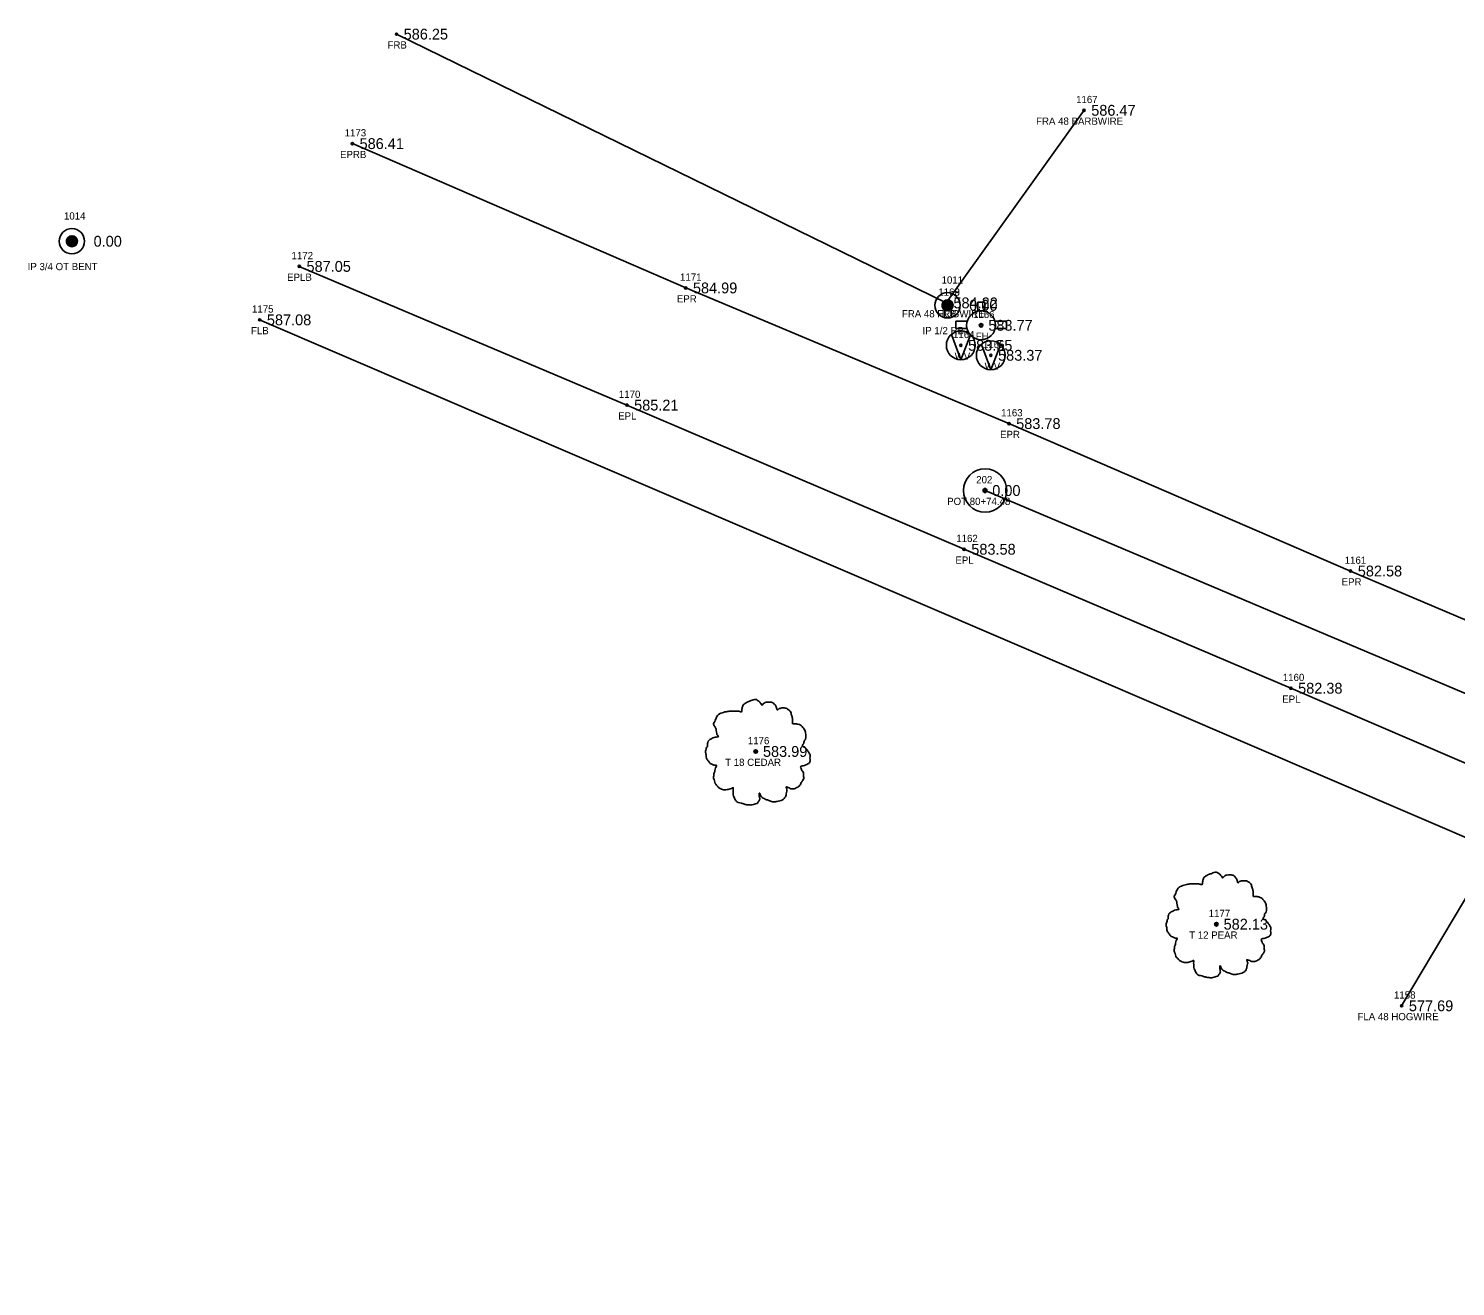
# Model space of a CAD drawing. Extents: x 1664393 to 1667175, y 987029 to 988607.
# Drawn here: x 1664830.8 to 1665028.1, y 987885.7 to 988059.7 of the extents above; entities that cross this region are included whole.
import ezdxf

# ---------------------------------------------------------------- set-up
doc = ezdxf.new("R2010")
doc.units = 0
for name, color, linetype in [('RD_EX_DV_Prop_txCode', 7, 'Continuous'), ('RD_EX_DV_PropPin', 7, 'Continuous'), ('RD_EX_Fence_Other', 7, 'Continuous'), ('RD_EX_Fence_Other_txCode', 7, 'Continuous'), ('RD_EX_Road', 7, 'Continuous'), ('RD_EX_Road_txCode', 7, 'Continuous'), ('RD_EX_TX_DV_Prop_ELEV', 7, 'Continuous'), ('RD_EX_TX_Fence_Other_ELEV', 7, 'Continuous'), ('RD_EX_TX_Road_ELEV', 7, 'Continuous'), ('RD_EX_TX_UT_ELEV', 7, 'Continuous'), ('RD_EX_TX_VEG_ELEV', 7, 'Continuous'), ('RD_EX_UT', 7, 'Continuous'), ('RD_EX_UT_txCode', 7, 'Continuous'), ('RD_EX_VEG', 7, 'Continuous'), ('RD_EX_VEG_txCode', 7, 'Continuous'), ('RD_HC_Cl', 7, 'Continuous'), ('RD_HC_Data', 7, 'Continuous'), ('RD_HC_Survey_ELEV', 7, 'Continuous'), ('RD_HC_txCode', 7, 'Continuous'), ('RD_SMD_Locator', 7, 'Continuous')]:
    doc.layers.add(name, color=color, linetype=linetype)

msp = doc.modelspace()

# ---------------------------------------------------------------- linework, layer by layer
at = {"layer": 'RD_EX_DV_PropPin'}
for p, q in [((1664836.03, 988030.1), (1664836.03, 988030.49)), ((1664836.06, 988030), (1664836.06, 988030.59)), ((1664836.1, 988029.92), (1664836.1, 988030.66)), ((1664836.13, 988029.87), (1664836.13, 988030.72)), ((1664836.17, 988029.82), (1664836.17, 988030.77)), ((1664836.2, 988029.78), (1664836.2, 988030.81)), ((1664836.24, 988029.74), (1664836.24, 988030.84)), ((1664836.27, 988029.71), (1664836.27, 988030.88)), ((1664836.31, 988029.68), (1664836.31, 988030.9)), ((1664836.34, 988029.66), (1664836.34, 988030.93)), ((1664836.38, 988029.64), (1664836.38, 988030.95)), ((1664836.41, 988029.62), (1664836.41, 988030.97)), ((1664836.45, 988029.6), (1664836.45, 988030.99)), ((1664836.48, 988029.59), (1664836.48, 988031)), ((1664836.52, 988029.57), (1664836.52, 988031.01)), ((1664836.55, 988029.56), (1664836.55, 988031.03)), ((1664836.59, 988029.55), (1664836.59, 988031.03)), ((1664836.62, 988029.55), (1664836.62, 988031.04)), ((1664836.66, 988029.54), (1664836.66, 988031.05)), ((1664836.69, 988029.54), (1664836.69, 988031.05)), ((1664836.73, 988029.53), (1664836.73, 988031.05)), ((1664836.76, 988029.53), (1664836.76, 988031.05)), ((1664836.8, 988029.53), (1664836.8, 988031.05)), ((1664836.83, 988029.54), (1664836.83, 988031.05)), ((1664836.87, 988029.54), (1664836.87, 988031.05)), ((1664836.9, 988029.55), (1664836.9, 988031.04)), ((1664836.94, 988029.55), (1664836.94, 988031.03)), ((1664836.97, 988029.56), (1664836.97, 988031.03)), ((1664837.01, 988029.57), (1664837.01, 988031.01)), ((1664837.04, 988029.59), (1664837.04, 988031)), ((1664837.08, 988029.6), (1664837.08, 988030.99)), ((1664837.11, 988029.62), (1664837.11, 988030.97)), ((1664837.15, 988029.64), (1664837.15, 988030.95)), ((1664837.18, 988029.66), (1664837.18, 988030.93)), ((1664837.22, 988029.68), (1664837.22, 988030.9)), ((1664837.25, 988029.71), (1664837.25, 988030.88)), ((1664837.29, 988029.74), (1664837.29, 988030.84)), ((1664837.32, 988029.78), (1664837.32, 988030.81)), ((1664837.36, 988029.82), (1664837.36, 988030.77)), ((1664837.39, 988029.87), (1664837.39, 988030.72)), ((1664837.43, 988029.92), (1664837.43, 988030.66)), ((1664837.46, 988030), (1664837.46, 988030.59)), ((1664837.5, 988030.1), (1664837.5, 988030.49)), ((1664957.14, 988021.23), (1664957.14, 988021.62)), ((1664957.17, 988021.13), (1664957.17, 988021.72)), ((1664957.21, 988021.06), (1664957.21, 988021.79)), ((1664957.24, 988021), (1664957.24, 988021.85)), ((1664957.28, 988020.95), (1664957.28, 988021.9)), ((1664957.31, 988020.91), (1664957.31, 988021.94)), ((1664957.35, 988020.87), (1664957.35, 988021.98)), ((1664957.38, 988020.84), (1664957.38, 988022.01)), ((1664957.42, 988020.82), (1664957.42, 988022.04)), ((1664957.46, 988020.79), (1664957.46, 988022.06)), ((1664957.49, 988020.77), (1664957.49, 988022.08)), ((1664957.53, 988020.75), (1664957.53, 988022.1)), ((1664957.56, 988020.73), (1664957.56, 988022.12)), ((1664957.6, 988020.72), (1664957.6, 988022.13)), ((1664957.63, 988020.7), (1664957.63, 988022.15)), ((1664957.67, 988020.69), (1664957.67, 988022.16)), ((1664957.7, 988020.68), (1664957.7, 988022.17)), ((1664957.74, 988020.68), (1664957.74, 988022.17)), ((1664957.77, 988020.67), (1664957.77, 988022.18)), ((1664957.81, 988020.67), (1664957.81, 988022.18)), ((1664957.84, 988020.66), (1664957.84, 988022.19)), ((1664957.88, 988020.66), (1664957.88, 988022.19)), ((1664957.91, 988020.66), (1664957.91, 988022.19)), ((1664957.95, 988020.67), (1664957.95, 988022.18)), ((1664957.98, 988020.67), (1664957.98, 988022.18)), ((1664958.02, 988020.68), (1664958.02, 988022.17)), ((1664958.05, 988020.68), (1664958.05, 988022.17)), ((1664958.09, 988020.69), (1664958.09, 988022.16)), ((1664958.12, 988020.7), (1664958.12, 988022.15)), ((1664958.16, 988020.72), (1664958.16, 988022.13)), ((1664958.19, 988020.73), (1664958.19, 988022.12)), ((1664958.23, 988020.75), (1664958.23, 988022.1)), ((1664958.26, 988020.77), (1664958.26, 988022.08)), ((1664958.3, 988020.79), (1664958.3, 988022.06)), ((1664958.33, 988020.82), (1664958.33, 988022.04)), ((1664958.37, 988020.84), (1664958.37, 988022.01)), ((1664958.4, 988020.87), (1664958.4, 988021.98)), ((1664958.44, 988020.91), (1664958.44, 988021.94)), ((1664958.47, 988020.95), (1664958.47, 988021.9)), ((1664958.51, 988021), (1664958.51, 988021.85)), ((1664958.54, 988021.06), (1664958.54, 988021.79)), ((1664958.58, 988021.13), (1664958.58, 988021.72)), ((1664958.61, 988021.23), (1664958.61, 988021.62))]:
    msp.add_line(p, q, dxfattribs=at)
for centre, radius in [((1664836.76, 988030.29), 1.75), ((1664836.76, 988030.29), 0.761), ((1664957.88, 988021.43), 1.75), ((1664957.88, 988021.43), 0.761)]:
    msp.add_circle(centre, radius, dxfattribs=at)
at = {"layer": 'RD_EX_Fence_Other'}
for points in [[(1664976.76, 988048.41), (1664957.7, 988021.76), (1664957.7, 988021.76), (1664881.65, 988058.95)], [(1665020.7, 987924.5), (1665033.54, 987946.09), (1664862.73, 988019.42)]]:
    msp.add_lwpolyline(points, dxfattribs=at)
at = {"layer": 'RD_EX_Road'}
for points in [[(1665506.06, 987776.52), (1665471.95, 987789.57), (1665426.52, 987809.19), (1665380.33, 987828.78), (1665335.61, 987847.53), (1665288.25, 987866.82), (1665242.34, 987886.56), (1665197.07, 987906.16), (1665152.2, 987925.43), (1665127.55, 987936.7), (1665104.5, 987945.2), (1665059.19, 987965.3), (1665013.63, 987984.66), (1664966.38, 988005.06), (1664921.66, 988023.83), (1664875.55, 988043.8)], [(1665498.75, 987759.37), (1665465.87, 987774.2), (1665419.78, 987793.88), (1665373.62, 987813.14), (1665327.95, 987832.31), (1665281.42, 987852.3), (1665236.13, 987871.34), (1665189.6, 987890.71), (1665143.92, 987909.97), (1665117.43, 987920.99), (1665086.22, 987934.27), (1665051.62, 987948.55), (1665005.38, 987968.44), (1664960.17, 987987.67), (1664913.53, 988007.62), (1664868.21, 988026.81)]]:
    msp.add_lwpolyline(points, dxfattribs=at)
at = {"layer": 'RD_EX_UT'}
for p, q in [((1664962.06, 988021.88), (1664962.06, 988020.61)), ((1664963.06, 988021.88), (1664962.06, 988021.88)), ((1664963.06, 988020.58), (1664963.06, 988021.88)), ((1664960.6, 988019.23), (1664959.04, 988019.23)), ((1664959.04, 988019.23), (1664959.04, 988018.23)), ((1664959.04, 988018.23), (1664960.56, 988018.23)), ((1664966.04, 988019.23), (1664964.43, 988019.23)), ((1664964.47, 988018.23), (1664966.04, 988018.23)), ((1664966.04, 988018.23), (1664966.04, 988019.23)), ((1664959.72, 988013.9), (1664958.42, 988017.38)), ((1664959.72, 988013.9), (1664961.05, 988017.35)), ((1664963.87, 988012.51), (1664962.57, 988016)), ((1664963.87, 988012.51), (1664965.19, 988015.96))]:
    msp.add_line(p, q, dxfattribs=at)
for centre, radius in [((1664962.52, 988018.66), 2), ((1664959.72, 988015.89), 2), ((1664962.52, 988018.66), 0.25), ((1664963.87, 988014.51), 2)]:
    msp.add_circle(centre, radius, dxfattribs=at)
for start, end in [(74.2455, 103.2128), (163.3387, 192.315), (347.685, 16.6613)]:
    msp.add_arc((1664962.52, 988018.66), 2, start, end, dxfattribs=at)
at = {"layer": 'RD_EX_VEG'}
for centre, radius in [((1664931.35, 987959.69), 0.25), ((1664931.34, 987959.67), 0.0001), ((1664995.07, 987935.79), 0.25), ((1664995.06, 987935.77), 0.0001)]:
    msp.add_circle(centre, radius, dxfattribs=at)
for points in [[(1664931.48, 987966.86), (1664931.18, 987966.88), (1664930.86, 987966.78), (1664930.61, 987966.68), (1664930.38, 987966.61), (1664930.16, 987966.51), (1664929.86, 987966.33), (1664929.63, 987966.13), (1664929.51, 987965.88), (1664929.46, 987965.66), (1664929.41, 987965.38), (1664929.41, 987965.21), (1664929.28, 987965.18), (1664929.13, 987965.21), (1664928.88, 987965.28), (1664928.63, 987965.28), (1664928.38, 987965.28), (1664928.03, 987965.26), (1664927.68, 987965.26), (1664927.41, 987965.21), (1664927.08, 987965.16), (1664926.71, 987965.03), (1664926.36, 987964.91), (1664926.06, 987964.66), (1664925.81, 987964.18), (1664925.68, 987963.83), (1664925.53, 987963.58), (1664925.68, 987963.13), (1664925.86, 987962.78), (1664925.88, 987962.58), (1664925.96, 987962.16), (1664926.06, 987961.93), (1664926.18, 987961.73), (1664926.11, 987961.71), (1664925.73, 987961.66), (1664925.43, 987961.56), (1664925.01, 987961.33), (1664924.78, 987961.11), (1664924.68, 987960.78), (1664924.66, 987960.43), (1664924.56, 987960.23), (1664924.48, 987959.96), (1664924.46, 987959.88), (1664924.41, 987959.56), (1664924.51, 987959.11), (1664924.53, 987958.76), (1664924.66, 987958.53), (1664924.81, 987958.36), (1664924.98, 987958.11), (1664925.38, 987957.88), (1664925.71, 987957.78), (1664925.91, 987957.76), (1664925.73, 987957.26), (1664925.68, 987956.91), (1664925.56, 987956.51), (1664925.56, 987956.44), (1664925.51, 987955.96), (1664925.66, 987955.64), (1664925.73, 987955.26), (1664925.91, 987955.04), (1664926.18, 987954.74), (1664926.51, 987954.51), (1664927.01, 987954.39), (1664927.41, 987954.41), (1664927.98, 987954.59), (1664928.23, 987954.66), (1664928.21, 987954.49), (1664928.23, 987954.11), (1664928.23, 987953.69), (1664928.38, 987953.36), (1664928.48, 987953.09), (1664928.63, 987952.84), (1664928.96, 987952.61), (1664929.36, 987952.54), (1664929.78, 987952.39), (1664930.23, 987952.31), (1664930.73, 987952.29), (1664931.33, 987952.44), (1664931.61, 987952.56), (1664931.71, 987952.74), (1664931.91, 987953.11), (1664931.86, 987953.34), (1664931.88, 987953.94), (1664931.98, 987953.76), (1664932.16, 987953.41), (1664932.66, 987953.11), (1664933.06, 987952.94), (1664933.53, 987952.79), (1664933.83, 987952.71), (1664934.31, 987952.79), (1664934.68, 987952.86), (1664935.05, 987952.99), (1664935.35, 987953.26), (1664935.53, 987953.54), (1664935.58, 987953.81), (1664935.65, 987954.19), (1664935.7, 987954.36)], [(1664935.7, 987954.36), (1664935.63, 987954.54), (1664935.58, 987954.79), (1664935.65, 987954.76), (1664935.83, 987954.71), (1664936.1, 987954.59), (1664936.33, 987954.51), (1664936.65, 987954.54), (1664936.93, 987954.64), (1664937.38, 987954.91), (1664937.65, 987955.39), (1664937.93, 987955.79), (1664938, 987956.11), (1664937.95, 987956.34), (1664937.93, 987956.83), (1664937.73, 987957.08), (1664937.68, 987957.21), (1664937.58, 987957.61), (1664937.65, 987957.66), (1664937.93, 987957.71), (1664938.3, 987957.83), (1664938.58, 987957.96), (1664938.8, 987958.13), (1664938.88, 987958.36), (1664938.85, 987958.76), (1664938.9, 987959.16), (1664938.83, 987959.31), (1664938.73, 987959.46), (1664938.65, 987959.66), (1664938.5, 987959.81), (1664938.4, 987959.96), (1664938.3, 987960.06), (1664938.18, 987960.21), (1664938, 987960.33), (1664937.85, 987960.38), (1664937.8, 987960.53), (1664937.95, 987960.73), (1664938, 987960.83), (1664938.03, 987961.06), (1664938.25, 987961.41), (1664938.3, 987961.81), (1664938.25, 987962.23), (1664938.2, 987962.51), (1664938.05, 987962.78), (1664937.85, 987963.03), (1664937.73, 987963.21), (1664937.55, 987963.33), (1664937.23, 987963.46), (1664936.98, 987963.51), (1664936.63, 987963.51), (1664936.43, 987963.56), (1664936.45, 987963.61), (1664936.45, 987963.76), (1664936.45, 987964.03), (1664936.38, 987964.48), (1664936.23, 987964.98), (1664936.23, 987965.01), (1664936.13, 987965.26), (1664935.9, 987965.46), (1664935.73, 987965.56), (1664935.53, 987965.68), (1664935.28, 987965.71), (1664934.98, 987965.71), (1664934.71, 987965.66), (1664934.51, 987965.56), (1664934.33, 987965.43), (1664934.26, 987965.58), (1664934.16, 987965.88), (1664934.11, 987966.03), (1664933.96, 987966.21), (1664933.73, 987966.41), (1664933.28, 987966.53), (1664932.66, 987966.46), (1664932.36, 987966.26), (1664932.21, 987966.08), (1664932.16, 987966.21), (1664931.96, 987966.41), (1664931.86, 987966.58), (1664931.68, 987966.71), (1664931.53, 987966.81), (1664931.43, 987966.86)], [(1664995.2, 987942.96), (1664994.9, 987942.98), (1664994.58, 987942.88), (1664994.33, 987942.78), (1664994.1, 987942.71), (1664993.88, 987942.61), (1664993.58, 987942.43), (1664993.35, 987942.23), (1664993.23, 987941.98), (1664993.18, 987941.76), (1664993.13, 987941.48), (1664993.13, 987941.31), (1664993, 987941.28), (1664992.85, 987941.31), (1664992.6, 987941.38), (1664992.35, 987941.38), (1664992.1, 987941.38), (1664991.75, 987941.36), (1664991.4, 987941.36), (1664991.13, 987941.31), (1664990.8, 987941.26), (1664990.43, 987941.13), (1664990.08, 987941.01), (1664989.78, 987940.76), (1664989.53, 987940.28), (1664989.4, 987939.93), (1664989.25, 987939.68), (1664989.4, 987939.23), (1664989.58, 987938.88), (1664989.6, 987938.68), (1664989.68, 987938.26), (1664989.78, 987938.03), (1664989.9, 987937.83), (1664989.83, 987937.81), (1664989.45, 987937.76), (1664989.15, 987937.66), (1664988.73, 987937.43), (1664988.5, 987937.21), (1664988.4, 987936.88), (1664988.38, 987936.53), (1664988.28, 987936.33), (1664988.21, 987936.06), (1664988.18, 987935.98), (1664988.13, 987935.66), (1664988.23, 987935.21), (1664988.26, 987934.86), (1664988.38, 987934.63), (1664988.53, 987934.46), (1664988.7, 987934.21), (1664989.1, 987933.98), (1664989.43, 987933.88), (1664989.63, 987933.86), (1664989.45, 987933.36), (1664989.4, 987933.01), (1664989.28, 987932.61), (1664989.28, 987932.53), (1664989.23, 987932.06), (1664989.38, 987931.74), (1664989.45, 987931.36), (1664989.63, 987931.14), (1664989.9, 987930.84), (1664990.23, 987930.61), (1664990.73, 987930.49), (1664991.13, 987930.51), (1664991.7, 987930.69), (1664991.95, 987930.76), (1664991.93, 987930.59), (1664991.95, 987930.21), (1664991.95, 987929.79), (1664992.1, 987929.46), (1664992.2, 987929.19), (1664992.35, 987928.94), (1664992.68, 987928.71), (1664993.08, 987928.64), (1664993.5, 987928.49), (1664993.95, 987928.41), (1664994.45, 987928.39), (1664995.05, 987928.54), (1664995.33, 987928.66), (1664995.43, 987928.84), (1664995.63, 987929.21), (1664995.58, 987929.44), (1664995.6, 987930.04), (1664995.7, 987929.86), (1664995.88, 987929.51), (1664996.38, 987929.21), (1664996.78, 987929.04), (1664997.25, 987928.89), (1664997.55, 987928.81), (1664998.03, 987928.89), (1664998.4, 987928.96), (1664998.78, 987929.09), (1664999.08, 987929.36), (1664999.25, 987929.64), (1664999.3, 987929.91), (1664999.38, 987930.29), (1664999.43, 987930.46)], [(1664999.43, 987930.46), (1664999.35, 987930.64), (1664999.3, 987930.89), (1664999.38, 987930.86), (1664999.55, 987930.81), (1664999.83, 987930.69), (1665000.05, 987930.61), (1665000.37, 987930.64), (1665000.65, 987930.74), (1665001.1, 987931.01), (1665001.37, 987931.49), (1665001.65, 987931.89), (1665001.72, 987932.21), (1665001.67, 987932.43), (1665001.65, 987932.93), (1665001.45, 987933.18), (1665001.4, 987933.31), (1665001.3, 987933.71), (1665001.37, 987933.76), (1665001.65, 987933.81), (1665002.02, 987933.93), (1665002.3, 987934.06), (1665002.52, 987934.23), (1665002.6, 987934.46), (1665002.57, 987934.86), (1665002.62, 987935.26), (1665002.55, 987935.41), (1665002.45, 987935.56), (1665002.37, 987935.76), (1665002.22, 987935.91), (1665002.12, 987936.06), (1665002.02, 987936.16), (1665001.9, 987936.31), (1665001.72, 987936.43), (1665001.57, 987936.48), (1665001.52, 987936.63), (1665001.67, 987936.83), (1665001.72, 987936.93), (1665001.75, 987937.16), (1665001.97, 987937.51), (1665002.02, 987937.91), (1665001.97, 987938.33), (1665001.92, 987938.61), (1665001.77, 987938.88), (1665001.57, 987939.13), (1665001.45, 987939.31), (1665001.27, 987939.43), (1665000.95, 987939.56), (1665000.7, 987939.61), (1665000.35, 987939.61), (1665000.15, 987939.66), (1665000.17, 987939.71), (1665000.17, 987939.86), (1665000.17, 987940.13), (1665000.1, 987940.58), (1664999.95, 987941.08), (1664999.95, 987941.11), (1664999.85, 987941.36), (1664999.63, 987941.56), (1664999.45, 987941.66), (1664999.25, 987941.78), (1664999, 987941.81), (1664998.7, 987941.81), (1664998.43, 987941.76), (1664998.23, 987941.66), (1664998.05, 987941.53), (1664997.98, 987941.68), (1664997.88, 987941.98), (1664997.83, 987942.13), (1664997.68, 987942.31), (1664997.45, 987942.51), (1664997, 987942.63), (1664996.38, 987942.56), (1664996.08, 987942.36), (1664995.93, 987942.18), (1664995.88, 987942.31), (1664995.68, 987942.51), (1664995.58, 987942.68), (1664995.4, 987942.81), (1664995.25, 987942.91), (1664995.15, 987942.96)]]:
    msp.add_spline(points, degree=3, dxfattribs=at)
at = {"layer": 'RD_HC_Cl'}
msp.add_line((1666160.05, 987489.41), (1664963.07, 987995.8), dxfattribs=at)
at = {"layer": 'RD_HC_Data'}
for radius in [3, 0.282]:
    msp.add_circle((1664963.07, 987995.8), radius, dxfattribs=at)
at = {"layer": 'RD_SMD_Locator'}
for centre in [(1664881.65, 988058.95), (1664976.76, 988048.41), (1664875.55, 988043.8), (1664836.76, 988030.29), (1664868.21, 988026.81), (1664921.66, 988023.83), (1664957.7, 988021.76), (1664957.7, 988021.76), (1664957.88, 988021.43), (1664862.73, 988019.42), (1664962.52, 988018.66), (1664959.72, 988015.89), (1664963.87, 988014.51), (1664913.53, 988007.62), (1664966.38, 988005.06), (1664963.07, 987995.8), (1664960.17, 987987.67), (1665013.63, 987984.66), (1665005.38, 987968.44), (1664931.35, 987959.69), (1664995.07, 987935.79), (1665020.7, 987924.5)]:
    msp.add_circle(centre, 0.15, dxfattribs=at)

# ---------------------------------------------------------------- texts
at = {"layer": 'RD_EX_DV_Prop_txCode'}
for s, p in [('1014', (1664835.66, 988033.29)), ('IP 3/4 OT BENT', (1664830.64, 988026.29)), ('1011', (1664957.06, 988024.43)), ('IP 1/2 RB', (1664954.43, 988017.43))]:
    msp.add_text(s, height=1, dxfattribs=at).set_placement(p)
at = {"layer": 'RD_EX_Fence_Other_txCode'}
for s, p in [('FRB', (1664880.42, 988056.95)), ('1167', (1664975.67, 988049.41)), ('FRA 48 BARBWIRE', (1664970.13, 988046.41)), ('1168', (1664956.61, 988022.76)), ('1169', (1664956.61, 988022.76)), ('1175', (1664861.67, 988020.42)), ('FRA 48 HOGWIRE', (1664951.57, 988019.76)), ('FRB', (1664956.47, 988019.76)), ('FLB', (1664861.53, 988017.42)), ('1158', (1665019.64, 987925.5)), ('FLA 48 HOGWIRE', (1665014.59, 987922.5))]:
    msp.add_text(s, height=1, dxfattribs=at).set_placement(p)
at = {"layer": 'RD_EX_Road_txCode'}
for s, p in [('1173', (1664874.49, 988044.8)), ('EPRB', (1664873.85, 988041.8)), ('1172', (1664867.14, 988027.81)), ('EPLB', (1664866.53, 988024.81)), ('1171', (1664920.88, 988024.83)), ('EPR', (1664920.44, 988021.83)), ('1170', (1664912.42, 988008.62)), ('EPL', (1664912.32, 988005.62)), ('1163', (1664965.29, 988006.06)), ('EPR', (1664965.15, 988003.06)), ('1162', (1664959.09, 987988.67)), ('EPL', (1664958.97, 987985.67)), ('1161', (1665012.82, 987985.66)), ('EPR', (1665012.4, 987982.66)), ('1160', (1665004.26, 987969.44)), ('EPL', (1665004.18, 987966.44))]:
    msp.add_text(s, height=1, dxfattribs=at).set_placement(p)
at = {"layer": 'RD_EX_TX_DV_Prop_ELEV'}
for p in [(1664839.76, 988029.54), (1664960.88, 988020.68)]:
    msp.add_text('0.00', height=1.5, dxfattribs=at).set_placement(p)
at = {"layer": 'RD_EX_TX_Fence_Other_ELEV'}
for s, p in [('586.25', (1664882.65, 988058.2)), ('586.47', (1664977.76, 988047.66)), ('584.22', (1664958.7, 988021.01)), ('584.22', (1664958.7, 988021.01)), ('587.08', (1664863.73, 988018.67)), ('577.69', (1665021.7, 987923.75))]:
    msp.add_text(s, height=1.5, dxfattribs=at).set_placement(p)
at = {"layer": 'RD_EX_TX_Road_ELEV'}
for s, p in [('586.41', (1664876.55, 988043.05)), ('587.05', (1664869.21, 988026.06)), ('584.99', (1664922.66, 988023.08)), ('585.21', (1664914.53, 988006.87)), ('583.78', (1664967.38, 988004.31)), ('583.58', (1664961.17, 987986.92)), ('582.58', (1665014.63, 987983.91)), ('582.38', (1665006.38, 987967.69))]:
    msp.add_text(s, height=1.5, dxfattribs=at).set_placement(p)
at = {"layer": 'RD_EX_TX_UT_ELEV'}
for s, p in [('583.77', (1664963.52, 988017.91)), ('583.55', (1664960.72, 988015.14)), ('583.37', (1664964.87, 988013.76))]:
    msp.add_text(s, height=1.5, dxfattribs=at).set_placement(p)
at = {"layer": 'RD_EX_TX_VEG_ELEV'}
for s, p in [('583.99', (1664932.35, 987958.94)), ('582.13', (1664996.07, 987935.04))]:
    msp.add_text(s, height=1.5, dxfattribs=at).set_placement(p)
at = {"layer": 'RD_EX_UT_txCode'}
for s, p in [('1166', (1664961.41, 988019.66)), ('1164', (1664958.64, 988016.89)), ('FH', (1664961.78, 988016.66)), ('1165', (1664962.78, 988015.51)), ('WV', (1664958.87, 988013.89)), ('WV', (1664963.01, 988012.51))]:
    msp.add_text(s, height=1, dxfattribs=at).set_placement(p)
at = {"layer": 'RD_EX_VEG_txCode'}
for s, p in [('1176', (1664930.26, 987960.69)), ('T 18 CEDAR', (1664927.12, 987957.69)), ('1177', (1664994.01, 987936.79)), ('T 12 PEAR', (1664991.31, 987933.79))]:
    msp.add_text(s, height=1, dxfattribs=at).set_placement(p)
at = {"layer": 'RD_HC_Survey_ELEV'}
msp.add_text('0.00', height=1.5, dxfattribs=at).set_placement((1664964.07, 987995.05))
at = {"layer": 'RD_HC_txCode'}
for s, p in [('202', (1664961.85, 987996.8)), ('POT 80+74.48', (1664957.83, 987993.8))]:
    msp.add_text(s, height=1, dxfattribs=at).set_placement(p)

doc.saveas('drawing.dxf')
